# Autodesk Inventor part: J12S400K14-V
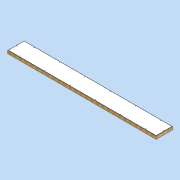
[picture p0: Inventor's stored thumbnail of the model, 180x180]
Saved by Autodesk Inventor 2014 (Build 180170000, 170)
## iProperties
Created: 2011-04
Part Number: J12S400K14-V
Document SubType Name: Modeling
Designer: david.appleford
Density: 1 g/cm^3
Description: Joist Spacer 3w x 400mm 14 Locks
Mass: 113575 g
Surface Area: 35228.5 cm^2
Volume: 113575 cm^3
Cost Center: £135.00
Material: Generic
Appearance: Wood (Pine)
Justset: False
Title: Panel 0.5w x 1w Locks 3
Author: david.appleford
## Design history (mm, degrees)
sketch "Sketch1"
  geometry: L1 (0, 0)-(3660, 0); L2 (3660, 0)-(3660, 468); L3 (3660, 468)-(0, 468); L4 (0, 468)-(0, 0); L5 (34, 434)-(3626, 434); L6 (3626, 434)-(3626, 34); L7 (3626, 34)-(34, 34); L8 (34, 34)-(34, 434)
  constraints: 16 end point, 4 parallel, 2 perpendicular, 1 horizontal, 3 other
  dimensions: "d0" = 3660 distance between parallel lines of L2 L4; "d1" = 468 distance between parallel lines of L1 L3; "d2" = 34 distance between parallel lines of L5 L3 (= 0.5 x t); "d30" = 400 distance between parallel lines of L7 L5 (derived); "d31" = 3592 distance between parallel lines of L6 L8 (derived)
extrude "Extrusion1" new body sketch "Sketch1" distance "d3" = 68 (= t); taper "d4" = 0 deg
sketch "Sketch2"
  geometry: L1 (3626, 434)-(3626, 34) reference; L2 (34, 434)-(3626, 434) reference; L3 (34, 34)-(34, 434) reference; L4 (3626, 34)-(34, 34) reference; L5 (3616, 424)-(3616, 44); L6 (3616, 44)-(44, 44); L7 (44, 44)-(44, 424); L8 (44, 424)-(3616, 424); 1 further point
  constraints: 8 end point, 3 other
  dimensions: "d5" = 10 distance between parallel lines of L8 L2
extrude "Extrusion2" join sketch "Sketch2" distance "d6" = 6 (= sw); taper "d7" = 0 deg
sketch "Sketch3"
  geometry: L1 (-44, 424)-(-3616, 424) reference; L2 (-3616, 424)-(-3616, 44) reference; L3 (-44, 44)-(-44, 424) reference; L4 (-3616, 44)-(-44, 44) reference; 1 further point
extrude "Extrusion3" join sketch "Sketch3" distance "d8" = 6 (= sw); taper "d9" = 0 deg
sketch "Sketch4" dims "d39" = 10
  geometry: L1 (34, 434)-(3626, 434) reference; L2 (3626, 434)-(3626, 34) reference; L3 (3626, 34)-(34, 34) reference; L4 (34, 34)-(34, 434) reference; 15 further points
  constraints: 3 horizontal alignment, 2 vertical alignment, 1 horizontal, 8 other
  dimensions: "d10" = 28 distance from line of point (305, 406) L1 (= k); "d12" = 28 distance from line of L3 point (915, 62) (= k); "d13" = 28 distance from line of point (62, 234) L4 (= k); "d14" = 305 horizontal distance of point (305, 406) point (0, 0) (= 0.25 x w); "d15" = 610 horizontal distance of point (915, 62) point (305, 406) (= 0.5 x w); "d29" = 28 distance from line of L2 point (3598, 234) (= d13); "d32" = 400 distance between parallel lines of L3 L1 (derived); "d33" = 200 distance from line of L1 point (62, 234) (= 0.5 x d32); "d36" = 1220 distance of point (305, 406) point (1525, 406)
hole "Hole1" sketch "Sketch4" at (305, 406), (62, 234), (915, 62), (3598, 234), (915, 406), (305, 62), (1525, 406), (1525, 62), (2135, 406), (2135, 62), (2745, 406), (2745, 62)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 diameter "d22" = 12 (= hd); stored, may be unused: countersink angle "d26" = 90 deg, drill point angle "d28" = 118 deg; dims "d23" = 6, "d24" = 4, "d25" = 2, "d27" = 8
sketch "Sketch5"
  geometry: L1 (-3626, 34)-(-34, 34) reference; L2 (-34, 434)-(-3626, 434) reference; L3 (-1176, 34)-(-1264, 34); L4 (-1264, 34)-(-1264, 434); L5 (-1264, 434)-(-1176, 434); L6 (-1176, 434)-(-1176, 34); L7 (-2484, 34)-(-2396, 34); L8 (-2396, 34)-(-2396, 434); L9 (-2396, 434)-(-2484, 434); L10 (-2484, 434)-(-2484, 34); L11 (-1220, 34)-(-1220, 434); L12 (-2440, 34)-(-2440, 434); 1 further point
  constraints: 20 end point, 4 midpoint, 4 point on line
  dimensions: "d41" = 1220 distance between parallel lines of L12 L11; "d42" = 88 distance between parallel lines of L4 L6; "d43" = 88 distance between parallel lines of L10 L8 (= d42); "d44" = 1220 distance from line of point (0, 0) L11 (= d41)
extrude "Extrusion4" cut sketch "Sketch5" stored distance "d45" = 10; taper "d46" = 0 deg
body "Solid1"
node "Projected Loop1"
other parameters: "t" = 68 [user parameter; used in 2 equation terms], "e" = 16 [user parameter], "sw" = 6 [user parameter; used in 2 equation terms], "sc" = 9 [user parameter], "sf" = 12 [user parameter], "k" = 28 [user parameter; used in 3 equation terms], "hd" = 12 [user parameter; used in 1 equation term]
